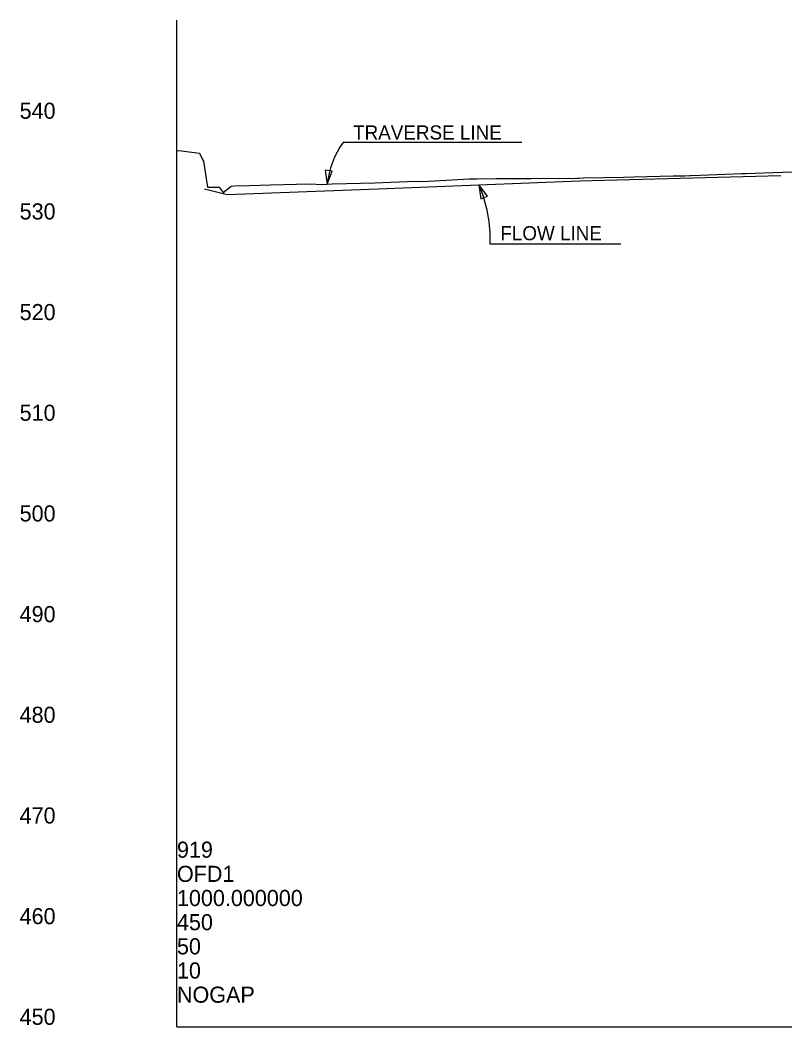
# Model space of a CAD drawing. Extents: x 49922 to 52614, y 49991 to 60509.
# Drawn here: x 49922 to 50305, y 57500 to 58000 of the extents above; entities that cross this region are included whole.
import ezdxf

# ---------------------------------------------------------------- set-up
doc = ezdxf.new("R2010")
doc.units = 0
for name, color, linetype in [('RD_DDB_ElevTX', 7, 'Continuous'), ('RD_DDB_Profile_EX', 7, 'Continuous'), ('RD_GPK_Profile_Cell', 7, 'Continuous'), ('RD_TX_Profile', 7, 'Continuous')]:
    doc.layers.add(name, color=color, linetype=linetype)

msp = doc.modelspace()

# ---------------------------------------------------------------- linework, layer by layer
at = {"layer": 'RD_DDB_Profile_EX'}
for points in [[(50000, 57935.12), (50000.68, 57935.22), (50002.22, 57935.03), (50011.14, 57934), (50012.68, 57930.8), (50013.23, 57929.99), (50015.21, 57917.09), (50020.88, 57917.03), (50022.88, 57914.45), (50026.7, 57917.33), (50027.05, 57917.59), (50028.57, 57917.78), (50036.04, 57917.91), (50046.48, 57918.18), (50065.83, 57918.68), (50072.2, 57918.31), (50077.06, 57918.69), (50098.26, 57919.22), (50118.38, 57920.06), (50122.1, 57919.91), (50145.12, 57921.12), (50148.86, 57921.17), (50158.73, 57921.3), (50173.84, 57921.38), (50175.95, 57921.41), (50198.76, 57921.56), (50199.59, 57921.57), (50202.16, 57921.63), (50221.96, 57922.08), (50227.16, 57922.16), (50246.5, 57922.6), (50252.17, 57922.68), (50254.75, 57922.78), (50255.38, 57922.81), (50259.89, 57923.05), (50280.39, 57923.8), (50282.46, 57923.9), (50305.4, 57924.73)], [(50013.73, 57916.15), (50025, 57913.45), (50100, 57916.15), (50200, 57920.2), (50300, 57922.8)]]:
    msp.add_lwpolyline(points, dxfattribs=at)
at = {"layer": 'RD_GPK_Profile_Cell'}
for q in [(50000, 58000), (50305.4, 57500), (50000, 57500)]:
    msp.add_line((50000, 57500), q, dxfattribs=at)
at = {"layer": 'RD_TX_Profile'}
for p, q in [((50171.32, 57939.21), (50082.47, 57939.21)), ((50220.45, 57888.69), (50155.6, 57888.69))]:
    msp.add_line(p, q, dxfattribs=at)
for points in [[(50073.54, 57925.41), (50074.63, 57918.5), (50077.14, 57925.03)], [(50154.3, 57912.65), (50150, 57918.18), (50150.96, 57911.24)]]:
    msp.add_lwpolyline(points, close=True, dxfattribs=at)
for centre, radius, start, end in [((50117.97, 57913.94), 43.57, 144.5456, 173.9897), ((50084.01, 57890.36), 71.62, 358.6658, 22.8561)]:
    msp.add_arc(centre, radius, start, end, dxfattribs=at)

# ---------------------------------------------------------------- texts
at = {"layer": 'RD_DDB_ElevTX'}
for s, p in [('540', (49921.86, 57951)), ('530', (49921.86, 57901)), ('520', (49921.86, 57851)), ('510', (49921.86, 57801)), ('500', (49921.86, 57751)), ('490', (49921.86, 57701)), ('480', (49921.86, 57651)), ('470', (49921.86, 57601)), ('460', (49921.86, 57551)), ('450', (49921.86, 57501))]:
    msp.add_text(s, height=8, dxfattribs=at).set_placement(p)
at = {"layer": 'RD_GPK_Profile_Cell'}
for s, p in [('919', (50000, 57584)), ('OFD1', (50000, 57572)), ('1000.000000', (50000, 57560)), ('450', (50000, 57548)), ('50', (50000, 57536)), ('10', (50000, 57524)), ('NOGAP', (50000, 57512))]:
    msp.add_text(s, height=8, dxfattribs=at).set_placement(p)
at = {"layer": 'RD_TX_Profile'}
for s, p in [('TRAVERSE LINE', (50087.47, 57940.71)), ('FLOW LINE', (50160.6, 57890.69))]:
    msp.add_text(s, height=7, dxfattribs=at).set_placement(p)

doc.saveas('drawing.dxf')
